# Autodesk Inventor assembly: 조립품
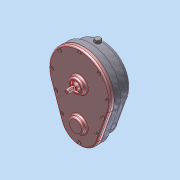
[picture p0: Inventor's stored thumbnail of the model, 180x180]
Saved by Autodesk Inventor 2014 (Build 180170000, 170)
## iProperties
Created: 2024-05
Part Number: 조립품
Document SubType Name: Assembly
Designer: dg
Author: dg
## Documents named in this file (15)
- C:\Users\dg\Desktop\740504V1002\조립품.iam
- C:\Users\dg\Desktop\740504V1002\본체.ipt
- C:\Users\dg\Desktop\740504V1002\가져온 구성요소\상단 축\상단 축.ipt
- C:\Users\dg\Desktop\740504V1002\가져온 구성요소\가스켓\가스켓.ipt
- C:\Users\dg\Desktop\740504V1002\가져온 구성요소\스퍼기어A\스퍼기어A.ipt
- C:\Users\dg\Desktop\740504V1002\가져온 구성요소\스퍼기어B\스퍼기어B.ipt
- C:\Users\dg\Desktop\740504V1002\가져온 구성요소\오일 실 10 20 4\오일 실 10 20 4.ipt
- C:\Users\dg\Desktop\740504V1002\가져온 구성요소\오일리스 부시\오일리스 부시.ipt
- C:\Users\dg\Desktop\740504V1002\가져온 구성요소\육각 머리 볼트  M6x0.75x6\육각 머리 볼트  M6x0.75x6.ipt
- C:\Users\dg\Desktop\740504V1002\가져온 구성요소\육각 소켓 머리 볼트 M4x10\육각 소켓 머리 볼트 M4x10.ipt
- C:\Users\dg\Desktop\740504V1002\가져온 구성요소\커버\커버.ipt
- C:\Users\dg\Desktop\740504V1002\가져온 구성요소\평행키 5x5x12\평행키 5x5x12.ipt
- C:\Users\dg\Desktop\740504V1002\가져온 구성요소\하단 축\하단 축.ipt
- C:\Users\dg\Desktop\740504V1002\가져온 구성요소\육각 소켓 머리 볼트 M4x10\육각 소켓 머리 볼트 M4x10_MIR.ipt
- C:\Users\dg\Desktop\740504V1002\가져온 구성요소\육각 소켓 머리 볼트 M4x10\육각 소켓 머리 볼트 M4x10_MIR1.ipt
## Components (2 placed, 2 different names)
1. 가스켓:1
2. 하단 축:1
